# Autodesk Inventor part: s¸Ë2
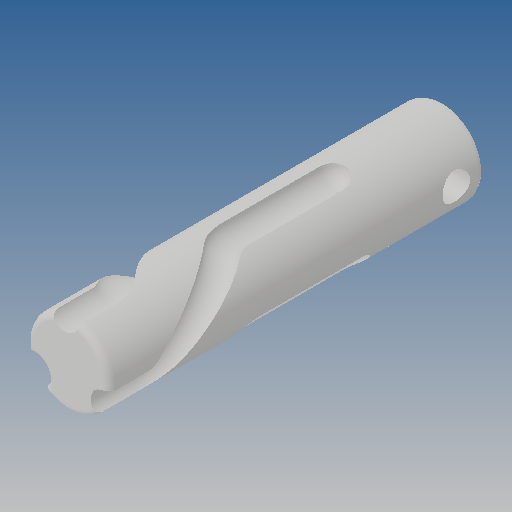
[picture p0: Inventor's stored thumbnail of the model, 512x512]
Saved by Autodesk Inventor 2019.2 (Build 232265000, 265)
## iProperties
Created: 2013-04
Part Number: s¸Ë2
Material: Ogólny
Document SubType Name: Modeling
Designer: CADENGINEERING4
Density: 1 g/cm^3
Appearance: Domyślna
Author: CADENGINEERING4
Revision Number: ÈÎºÎ
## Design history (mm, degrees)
feature "ÇÐ³ý-À­Éì1"
node "Bryła1"
